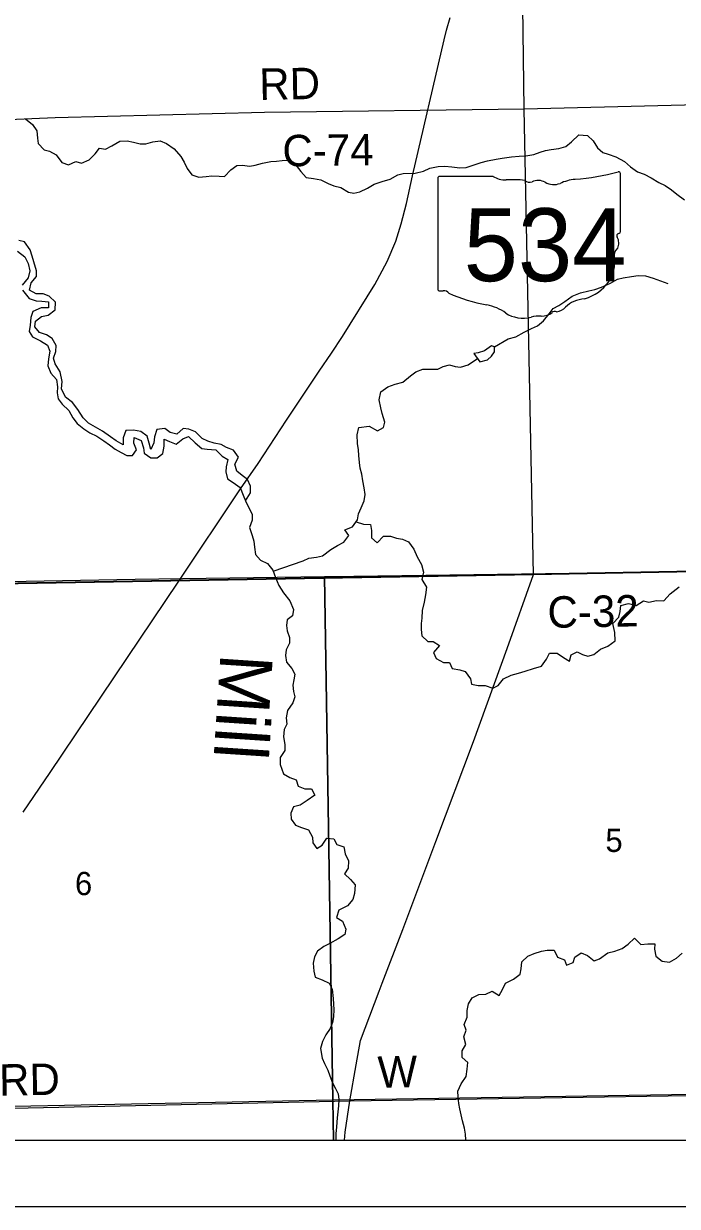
# Model space of a CAD drawing. Extents: x 0 to 34, y 0 to 22.
# Drawn here: x 4.215 to 5.396, y 13.887 to 16.025 of the extents above; entities that cross this region are included whole.
import ezdxf

# ---------------------------------------------------------------- set-up
doc = ezdxf.new("R2010")
doc.units = 0
for name, color, linetype in [('GM_X_Corporation', 7, 'Continuous'), ('GM_X_County_Road', 7, 'Continuous'), ('GM_X_County_Road_Text', 7, 'Continuous'), ('GM_X_Minor_Lake', 7, 'Continuous'), ('GM_X_Minor_River', 7, 'Continuous'), ('GM_X_Minor_River_Text', 7, 'Continuous'), ('GM_X_Rail_Line', 7, 'Continuous'), ('GM_X_Section_Text', 7, 'Continuous'), ('GM_X_State_Location', 7, 'Continuous'), ('GM_X_State_Route', 7, 'Continuous'), ('GM_X_State_Shield', 7, 'Continuous'), ('GM_X_Township_Road', 7, 'Continuous'), ('GM_X_Township_Road_Text', 7, 'Continuous'), ('SH_Data', 7, 'Continuous')]:
    doc.layers.add(name, color=color, linetype=linetype)

msp = doc.modelspace()

# ---------------------------------------------------------------- linework, layer by layer
at = {"layer": 'GM_X_Corporation'}
msp.add_lwpolyline([(2.9895, 20.1176), (2.9895, 14.989), (3.1061, 14.9902), (3.7218, 15.0051), (5.1362, 15.0301), (5.7825, 15.0418), (6.0746, 15.0468), (7.3134, 15.0684), (7.3375, 15.0689), (7.3129, 15.9614), (7.3097, 16.0633), (7.3049, 16.5704), (7.3046, 16.5913), (7.2998, 16.7507), (7.2943, 16.935), (7.2911, 17.0516), (7.2872, 17.1772), (7.283, 17.3071)], dxfattribs=at)
for points in [[(3.7367, 14.0069), (9.7895, 14.0069), (9.7895, 15.1275), (8.8365, 15.1033), (8.3803, 15.0917), (7.3375, 15.0689), (7.3134, 15.0684), (6.0746, 15.0468), (5.7825, 15.0418), (5.1362, 15.0301), (3.7218, 15.0051), (3.7359, 14.0555)], [(5.6513, 15.0385), (5.789, 15.0408), (5.8061, 14.0956), (4.774, 14.0793), (4.7584, 15.0257), (4.8116, 15.0266), (5.2442, 15.0326)], [(4.7584, 15.0257), (4.774, 14.0793), (3.7432, 14.0588), (3.7317, 15.0075), (3.9896, 15.013), (4.4166, 15.021)], [(4.7752, 14.0069), (5.8075, 14.0069), (5.8061, 14.0956), (4.774, 14.0793)], [(3.7439, 14.0069), (4.7752, 14.0069), (4.774, 14.0793), (3.7432, 14.0588)]]:
    msp.add_lwpolyline(points, close=True, dxfattribs=at)
at = {"layer": 'GM_X_County_Road'}
for points in [[(5.1195, 15.8708), (4.6505, 15.8645), (4.2722, 15.8551), (4.1739, 15.8504), (4.0083, 15.847), (3.8632, 15.8442), (3.7853, 15.842), (3.644, 15.8378), (3.5529, 15.8354), (3.4325, 15.8307), (3.1089, 15.8232)], [(3.722, 15.0045), (5.1364, 15.0296), (5.7827, 15.0412), (6.0748, 15.0463), (7.3136, 15.0678)], [(4.8042, 14.0781), (5.8006, 14.0939), (7.332, 14.1088)]]:
    msp.add_lwpolyline(points, dxfattribs=at)
at = {"layer": 'GM_X_Minor_Lake'}
for points in [[(5.039, 15.4137), (5.0529, 15.4174), (5.0604, 15.424), (5.0659, 15.4321), (5.0658, 15.4408), (5.0604, 15.4426), (5.0477, 15.4336), (5.036, 15.43), (5.0285, 15.4291)], [(5.0285, 15.4291), (5.039, 15.4137)]]:
    msp.add_lwpolyline(points, dxfattribs=at)
at = {"layer": 'GM_X_Minor_River'}
for points in [[(4.2189, 15.8528), (4.2312, 15.8428), (4.2394, 15.8312), (4.2404, 15.8183), (4.2417, 15.8084), (4.2525, 15.7972), (4.262, 15.7948), (4.2743, 15.7878), (4.2844, 15.7739), (4.2966, 15.77), (4.3097, 15.7759), (4.32, 15.7731), (4.3336, 15.779), (4.3443, 15.7899), (4.3525, 15.7999), (4.3635, 15.7982), (4.3744, 15.8041), (4.389, 15.8127), (4.4026, 15.813), (4.414, 15.8109), (4.4258, 15.8081), (4.4361, 15.8079), (4.4489, 15.8116), (4.4621, 15.8134), (4.4736, 15.8086), (4.487, 15.7986), (4.4994, 15.7852), (4.5053, 15.7747), (4.5108, 15.7634), (4.5193, 15.7521), (4.5315, 15.7478), (4.5448, 15.7488), (4.555, 15.7498), (4.5686, 15.7493), (4.5781, 15.7491), (4.5896, 15.7607), (4.6001, 15.7689), (4.6099, 15.7694), (4.6236, 15.7678), (4.6334, 15.7691), (4.647, 15.7728), (4.6617, 15.7757), (4.6723, 15.7763), (4.6825, 15.7776), (4.6928, 15.7782), (4.705, 15.7716), (4.7159, 15.7581), (4.7255, 15.7469), (4.7388, 15.7453), (4.7518, 15.7425), (4.7655, 15.7363), (4.7755, 15.7319), (4.788, 15.7287), (4.8018, 15.7203), (4.8117, 15.7186), (4.8223, 15.721), (4.8365, 15.7278), (4.8485, 15.7348), (4.8628, 15.7397), (4.8771, 15.7441), (4.891, 15.7516), (4.9008, 15.7544), (4.9224, 15.7548), (4.9375, 15.7586), (4.9492, 15.7637), (4.9642, 15.767), (4.976, 15.7673), (4.9889, 15.766), (5.0029, 15.7647), (5.0147, 15.7653), (5.0256, 15.769), (5.0418, 15.7742), (5.0531, 15.7771), (5.0686, 15.78), (5.0795, 15.7822), (5.0962, 15.7844), (5.1102, 15.7858), (5.1223, 15.786), (5.1366, 15.7886), (5.1483, 15.793), (5.1581, 15.7958), (5.1679, 15.7979), (5.1819, 15.7997), (5.1947, 15.803), (5.2048, 15.8115), (5.2178, 15.8239), (5.2334, 15.8227), (5.2438, 15.8134), (5.2516, 15.8006), (5.2612, 15.7925), (5.2711, 15.7892), (5.2849, 15.7842), (5.3006, 15.7757), (5.311, 15.7665), (5.324, 15.7572), (5.3358, 15.7529), (5.3485, 15.7463), (5.3627, 15.7378), (5.3741, 15.7327), (5.3856, 15.7246), (5.3952, 15.7168)], [(5.3952, 15.7168), (5.4087, 15.7068)], [(4.6159, 15.1626), (4.6251, 15.1768), (4.6249, 15.1893), (4.6197, 15.201), (4.6101, 15.2084), (4.6005, 15.2162), (4.5965, 15.229), (4.6034, 15.2417), (4.5945, 15.2544), (4.5819, 15.2588), (4.5719, 15.2643), (4.5594, 15.2667), (4.548, 15.2703), (4.5376, 15.2754), (4.526, 15.287), (4.5138, 15.2924), (4.5036, 15.2934), (4.492, 15.2833), (4.4798, 15.2861), (4.4702, 15.2935), (4.4562, 15.2917), (4.452, 15.278), (4.4502, 15.2677), (4.4448, 15.2554), (4.4419, 15.2668), (4.4383, 15.2796), (4.4268, 15.2877), (4.4138, 15.2905), (4.3998, 15.2895), (4.3951, 15.2765), (4.3954, 15.264), (4.3827, 15.2713), (4.3724, 15.2784), (4.3578, 15.2887), (4.3325, 15.3027), (4.3229, 15.3127), (4.3135, 15.3278), (4.3034, 15.3401), (4.2911, 15.3498), (4.2836, 15.3648), (4.2849, 15.3785), (4.2815, 15.3959), (4.2722, 15.4102), (4.2693, 15.4204), (4.2733, 15.4326), (4.2742, 15.4433), (4.2668, 15.456), (4.2564, 15.4627), (4.2439, 15.467), (4.2353, 15.4771), (4.237, 15.4874), (4.2479, 15.4956), (4.2596, 15.4984), (4.2723, 15.5078), (4.2728, 15.5215), (4.2616, 15.5327), (4.2505, 15.537), (4.238, 15.5368), (4.2258, 15.5434), (4.2289, 15.5567), (4.2386, 15.5679), (4.2384, 15.5782), (4.2339, 15.5948), (4.2307, 15.6046), (4.2271, 15.616), (4.217, 15.6306), (4.207, 15.6334)], [(4.2044, 15.6136), (4.2178, 15.6036), (4.2234, 15.5916), (4.2263, 15.5783), (4.2235, 15.5654), (4.2127, 15.5526)], [(5.0655, 15.4409), (5.0901, 15.4553), (5.1041, 15.459), (5.1195, 15.4673), (5.1326, 15.4743), (5.1435, 15.4787), (5.1539, 15.4881), (5.1643, 15.5004), (5.1717, 15.51), (5.1819, 15.5156), (5.1927, 15.5226), (5.2062, 15.5327), (5.2212, 15.5387), (5.2363, 15.5424), (5.2469, 15.5445), (5.2589, 15.5489), (5.2751, 15.5561), (5.2878, 15.5632), (5.298, 15.5656), (5.3131, 15.5682), (5.3252, 15.5696), (5.3385, 15.5695), (5.3522, 15.5648), (5.3652, 15.5605), (5.3789, 15.5554)], [(4.2133, 15.5431), (4.2253, 15.5282), (4.2383, 15.5239), (4.2481, 15.5233), (4.2603, 15.522), (4.2601, 15.5114), (4.2468, 15.5115), (4.2318, 15.5047), (4.2282, 15.494), (4.2269, 15.4803), (4.2256, 15.4685), (4.2315, 15.4588), (4.2456, 15.4518), (4.2587, 15.4437), (4.2627, 15.4332), (4.2603, 15.4191), (4.259, 15.4065), (4.2645, 15.3933), (4.275, 15.3821), (4.2767, 15.3685), (4.2762, 15.3578), (4.2779, 15.3468), (4.2849, 15.3371), (4.2972, 15.3259), (4.3043, 15.3128), (4.3121, 15.3023), (4.324, 15.2926), (4.3351, 15.2852), (4.3474, 15.2794), (4.3604, 15.2709), (4.3704, 15.2639), (4.3804, 15.2557), (4.3918, 15.2502), (4.4018, 15.2443), (4.4117, 15.2445), (4.4194, 15.2549), (4.4143, 15.2666), (4.4148, 15.2773), (4.4274, 15.2718), (4.4318, 15.2586), (4.4328, 15.2487), (4.4451, 15.2402), (4.4568, 15.2401), (4.4665, 15.2482), (4.4693, 15.2616), (4.4691, 15.2741), (4.479, 15.2697), (4.4908, 15.265), (4.5028, 15.2744), (4.5129, 15.2791), (4.5253, 15.2676), (4.5372, 15.2572), (4.5471, 15.2558), (4.5623, 15.255), (4.5738, 15.2434), (4.5842, 15.2372), (4.5814, 15.2242), (4.5804, 15.2147), (4.5833, 15.2026), (4.5937, 15.1959), (4.6063, 15.1867), (4.6119, 15.1731), (4.6159, 15.1626)], [(4.6662, 15.0354), (4.7202, 15.0544), (4.7307, 15.0591), (4.7443, 15.0609), (4.7552, 15.0634), (4.7702, 15.0743), (4.7822, 15.0818), (4.7934, 15.0877), (4.8027, 15.1), (4.7957, 15.1101), (4.8092, 15.1153), (4.8185, 15.1284), (4.8198, 15.1391), (4.8252, 15.1502), (4.8303, 15.1624), (4.832, 15.1742), (4.8303, 15.186), (4.8281, 15.1989), (4.826, 15.2106), (4.8232, 15.2216), (4.8218, 15.2318), (4.8208, 15.2447), (4.8199, 15.2545), (4.8182, 15.2659), (4.8179, 15.2819), (4.8207, 15.2952), (4.8392, 15.2974), (4.8545, 15.289), (4.8654, 15.2949), (4.8679, 15.3048), (4.8626, 15.3207), (4.8602, 15.3309), (4.8576, 15.3449), (4.8604, 15.3594), (4.8731, 15.3684), (4.8863, 15.3736), (4.9002, 15.3772), (4.914, 15.3885), (4.9238, 15.3955), (4.9362, 15.4007), (4.9506, 15.4006), (4.9635, 15.4008), (4.9732, 15.4056), (4.9842, 15.4081), (4.9948, 15.4052), (5.0043, 15.4043), (5.0183, 15.4084), (5.0348, 15.4198)], [(4.6159, 15.1626), (4.6281, 15.1377), (4.6283, 15.1278), (4.6232, 15.1144), (4.628, 15.0997), (4.6312, 15.0895), (4.6322, 15.0789), (4.6343, 15.0657), (4.6429, 15.0552), (4.6555, 15.0493), (4.6656, 15.0374), (4.67, 15.0242), (4.6763, 15.0095), (4.6849, 14.9963), (4.6961, 14.9821), (4.7029, 14.9659), (4.7008, 14.9545), (4.6911, 14.9475), (4.6898, 14.9372), (4.6911, 14.9273), (4.6955, 14.9153), (4.6957, 14.9054), (4.6894, 14.8935), (4.6881, 14.8832), (4.6902, 14.8711), (4.6995, 14.8595), (4.7054, 14.849), (4.7033, 14.8391), (4.7016, 14.8295), (4.7026, 14.8182), (4.7054, 14.808), (4.7018, 14.7976), (4.6918, 14.7838), (4.6894, 14.7704), (4.6908, 14.7587), (4.6857, 14.7491), (4.6848, 14.7358), (4.6873, 14.7221), (4.6871, 14.7115), (4.6787, 14.6984), (4.6785, 14.6859), (4.6845, 14.6693), (4.696, 14.6627), (4.7078, 14.6583), (4.7114, 14.647), (4.7229, 14.6419), (4.735, 14.6421), (4.7413, 14.6305), (4.7275, 14.6207), (4.7147, 14.6125), (4.7027, 14.6096), (4.6979, 14.5978), (4.6985, 14.5871), (4.7063, 14.5763), (4.7174, 14.5719), (4.7299, 14.568), (4.737, 14.5544), (4.7376, 14.5442), (4.745, 14.5341), (4.7547, 14.5403), (4.7632, 14.553), (4.7757, 14.5518), (4.7808, 14.5416), (4.7934, 14.5373), (4.7963, 14.5244), (4.8018, 14.5116), (4.8013, 14.4987), (4.7951, 14.4883), (4.8055, 14.4783), (4.814, 14.4685), (4.8128, 14.4529), (4.8096, 14.4419), (4.8003, 14.4303), (4.7845, 14.4228), (4.7806, 14.4094), (4.7914, 14.4028), (4.7973, 14.3885), (4.7956, 14.3785), (4.7832, 14.3707), (4.7682, 14.3625), (4.7577, 14.3569), (4.7458, 14.3487), (4.7406, 14.3384), (4.7382, 14.3266), (4.7396, 14.3125), (4.7421, 14.3016), (4.7547, 14.2965), (4.7673, 14.2906), (4.7728, 14.2797), (4.7742, 14.2631), (4.7748, 14.2528), (4.7754, 14.2429), (4.7752, 14.23), (4.7732, 14.2197), (4.7692, 14.209), (4.7614, 14.1971), (4.7548, 14.1852), (4.7513, 14.1726), (4.7543, 14.1552), (4.759, 14.1454), (4.7645, 14.1333)], [(4.8159, 15.1248), (4.8292, 15.1206), (4.8417, 15.1197), (4.8434, 15.1091), (4.8433, 15.0958), (4.8541, 15.0869), (4.8652, 15.0985), (4.8781, 15.0984), (4.8888, 15.0948), (4.8998, 15.0931), (4.9101, 15.0884), (4.9199, 15.0749), (4.9258, 15.0613), (4.934, 15.0474), (4.9373, 15.0334), (4.9345, 15.0201), (4.9427, 15.0066), (4.9411, 14.9925), (4.9387, 14.9791), (4.9352, 14.9643), (4.9343, 14.9506), (4.9333, 14.9407), (4.9331, 14.93), (4.9345, 14.9183), (4.9453, 14.9086), (4.9548, 14.9084), (4.9663, 14.901), (4.9555, 14.8887), (4.9603, 14.8774), (4.9737, 14.8704), (4.9846, 14.8702), (4.989, 14.8597), (5.0031, 14.8569), (5.0126, 14.8541), (5.0223, 14.8409), (5.024, 14.8311), (5.0362, 14.8287), (5.0491, 14.8289), (5.0624, 14.8242), (5.0722, 14.829), (5.0818, 14.8406), (5.0957, 14.8477), (5.1093, 14.851), (5.1213, 14.8546), (5.1364, 14.8595), (5.1503, 14.8639), (5.1596, 14.8762), (5.1651, 14.887), (5.1791, 14.8872), (5.1902, 14.8791), (5.2013, 14.8725), (5.2042, 14.8839), (5.215, 14.8898), (5.2246, 14.8851), (5.2345, 14.8818), (5.2451, 14.8851), (5.2574, 14.8944), (5.2702, 14.8996), (5.2836, 14.9098), (5.283, 14.9246), (5.2796, 14.9408), (5.2904, 14.952), (5.2925, 14.9627), (5.2938, 14.9734), (5.3074, 14.9767), (5.3215, 14.9735), (5.3346, 14.9821), (5.3445, 14.9793), (5.3584, 14.9826), (5.3713, 14.9817), (5.3832, 14.9945), (5.3989, 15.0073)], [(5.0138, 14.0069), (5.0139, 14.0074), (5.0133, 14.018), (5.0116, 14.0287), (5.008, 14.0419), (5.0055, 14.0528), (5.003, 14.0634), (5.0013, 14.0733), (5.0003, 14.085), (4.9994, 14.0956), (5.0056, 14.1087), (5.0144, 14.1221), (5.0165, 14.1355), (5.0174, 14.1473), (5.0074, 14.1562), (5.0075, 14.1687), (5.0141, 14.1799), (5.0101, 14.1938), (5.0144, 14.2057), (5.0108, 14.2159), (5.0166, 14.2293), (5.0164, 14.2411), (5.0188, 14.2536), (5.0254, 14.264), (5.0374, 14.2703), (5.0503, 14.271), (5.0612, 14.2765), (5.0739, 14.2684), (5.0801, 14.2795), (5.0856, 14.2906), (5.0998, 14.2977), (5.1118, 14.3071), (5.1139, 14.3166), (5.1148, 14.3295), (5.1256, 14.3396), (5.1372, 14.3444), (5.1504, 14.3485), (5.1606, 14.3506), (5.1735, 14.3504), (5.1794, 14.3376), (5.1924, 14.3329), (5.196, 14.3231), (5.208, 14.3279), (5.2109, 14.3378), (5.2225, 14.3457), (5.2336, 14.3406), (5.2459, 14.3309), (5.2556, 14.3345), (5.2702, 14.3454), (5.283, 14.3487), (5.2962, 14.3535), (5.3071, 14.361), (5.3186, 14.3718), (5.3298, 14.3606), (5.3427, 14.362), (5.3552, 14.3619), (5.3546, 14.3524), (5.3571, 14.3395), (5.3683, 14.3302), (5.3816, 14.3286), (5.3943, 14.336), (5.4044, 14.345)], [(4.7645, 14.1333), (4.7685, 14.1232), (4.7733, 14.1107), (4.7784, 14.1006), (4.7835, 14.0908), (4.7848, 14.0802), (4.7839, 14.0688), (4.7826, 14.0581), (4.7813, 14.0471), (4.7801, 14.0311), (4.7792, 14.0185), (4.779, 14.0069)]]:
    msp.add_lwpolyline(points, dxfattribs=at)
at = {"layer": 'GM_X_Rail_Line'}
msp.add_lwpolyline([(4.2148, 14.5996), (4.263, 14.6716), (4.4942, 15.0158), (4.6068, 15.1841), (4.6388, 15.2299), (4.6903, 15.3085), (4.7492, 15.397), (4.7711, 15.4296), (4.7914, 15.4598), (4.8498, 15.5539), (4.8718, 15.5952), (4.8875, 15.632), (4.8974, 15.6635), (4.9069, 15.7001), (4.9179, 15.7499), (4.9748, 15.9956), (4.9788, 16.0131), (4.9854, 16.0365)], dxfattribs=at)
at = {"layer": 'GM_X_State_Route'}
for points in [[(5.1364, 15.0296), (5.1195, 15.8708), (5.1103, 16.5663)], [(4.8572, 14.2762), (4.8627, 14.2909), (4.9004, 14.3879), (4.96, 14.5469), (5.0275, 14.7277), (5.0888, 14.8954), (5.1364, 15.0296)], [(4.795, 14.0069), (4.7961, 14.0212), (4.8042, 14.0781), (4.8158, 14.143), (4.8237, 14.1872), (4.8572, 14.2762)]]:
    msp.add_lwpolyline(points, dxfattribs=at)
at = {"layer": 'GM_X_State_Shield'}
for p, q in [((4.9634, 15.7456), (4.9634, 15.5455)), ((5.0632, 15.749), (4.9667, 15.749)), ((5.293, 15.6493), (5.293, 15.754)), ((5.293, 15.6493), (5.293, 15.6493))]:
    msp.add_line(p, q, dxfattribs=at)
for centre, major_axis, start_param, end_param in [((5.1756, 16.0219), (0.3495, 0), 4.814394, 5.042369), ((5.2894, 15.7544), (0.00367, 0), 6.141152, 7.989035), ((4.9672, 15.746), (0.00382, 0), 1.712693, 3.28349), ((5.0862, 15.7723), (0.037, 0), 4.042523, 4.731795), ((5.0985, 15.6367), (0.133, 0), 1.404758, 1.657858), ((5.1287, 15.7471), (0.0107, 0), 3.836095, 5.185415), ((5.1443, 15.7239), (0.0222, 0), 0.950623, 2.079405), ((5.173, 15.7557), (0.0267, 0), 4.081561, 5.145723), ((5.2202, 15.6879), (0.0703, 0), 1.699011, 2.107814), ((5.2891, 15.6489), (0.00393, 0), 5.05454, 6.418171), ((5.2922, 15.6416), (0.00568, 0), 1.883978, 3.671073), ((5.2561, 15.6284), (0.0341, 0), 5.934695, 6.695948), ((5.3062, 15.6055), (0.0248, 0), 2.387724, 3.262537), ((5.1952, 15.5922), (0.0874, 0), 5.101752, 6.440018), ((4.9673, 15.545), (0.00385, 0), 3.00124, 4.508301), ((4.9678, 15.5655), (0.0294, 0), 4.665946, 4.897461), ((4.9739, 15.5339), (0.0106, 0), 0.519207, 1.627899), ((5.1077, 15.7137), (0.2524, 0), 4.195997, 4.488961), ((5.2321, 15.4893), (0.0479, 0), 1.647645, 2.488434), ((5.0324, 15.4556), (0.079, 0), 0.823519, 1.323587), ((5.1178, 15.5329), (0.0501, 0), 4.026481, 4.996735), ((5.1505, 15.5179), (0.0267, 0), 4.691044, 5.507374), ((5.1746, 15.4986), (0.00752, 0), 1.147584, 2.315152), ((5.1714, 15.5261), (0.0282, 0), 4.937069, 5.64225), ((5.1468, 15.4637), (0.0412, 0), 1.495662, 1.94098)]:
    msp.add_ellipse(centre, major_axis=major_axis, ratio=0.8, start_param=start_param, end_param=end_param, dxfattribs=at)
at = {"layer": 'GM_X_Township_Road'}
msp.add_line((3.7361, 14.055), (4.8042, 14.0781), dxfattribs=at)
msp.add_lwpolyline([(7.3131, 15.9608), (7.0513, 15.9556), (6.7947, 15.9481), (6.5899, 15.9475), (6.3611, 15.9388), (6.1369, 15.9328), (6.0463, 15.9282), (5.9481, 15.9181), (5.8864, 15.9123), (5.7783, 15.8996), (5.7151, 15.8908), (5.6504, 15.8839), (5.1195, 15.8708)], dxfattribs=at)
at = {"layer": 'SH_Data'}
msp.add_line((2.8945, 13.8873), (9.8945, 13.8873), dxfattribs=at)

# ---------------------------------------------------------------- texts
at = {"layer": 'GM_X_County_Road_Text'}
for s, height, rotation, p in [('RD', 0.05682, 0.9927, (4.6413, 15.8872)), ('C-74', 0.05682, 0.6858, (4.683, 15.767)), ('C-32', 0.05682, 1.0299, (5.1619, 14.9328)), ('W', 0.0568, 1.4494, (4.8554, 14.1013))]:
    msp.add_text(s, height=height, rotation=rotation, dxfattribs=at).set_placement(p)
at = {"layer": 'GM_X_Minor_River_Text'}
msp.add_text('Mill', height=0.09473, rotation=266.2116, dxfattribs=at).set_placement((4.571, 14.8877))
at = {"layer": 'GM_X_Section_Text'}
for s, p in [('5', (5.266, 14.5279)), ('6', (4.3081, 14.4499))]:
    msp.add_text(s, height=0.0419, rotation=0, dxfattribs=at).set_placement(p)
at = {"layer": 'GM_X_State_Location'}
for s in ['s', 'r']:
    msp.add_text(s, height=0.000189, dxfattribs=at).set_placement((5.1245, 15.6322))
msp.add_text('534', height=0.000189, rotation=0, dxfattribs=at).set_placement((5.0577, 15.6184))
at = {"layer": 'GM_X_State_Shield'}
msp.add_text('534', height=0.13184, dxfattribs=at).set_placement((5.01, 15.5596))
at = {"layer": 'GM_X_Township_Road_Text'}
msp.add_text('RD', height=0.05682, rotation=0.9891, dxfattribs=at).set_placement((4.1715, 14.0872))

doc.saveas('drawing.dxf')
